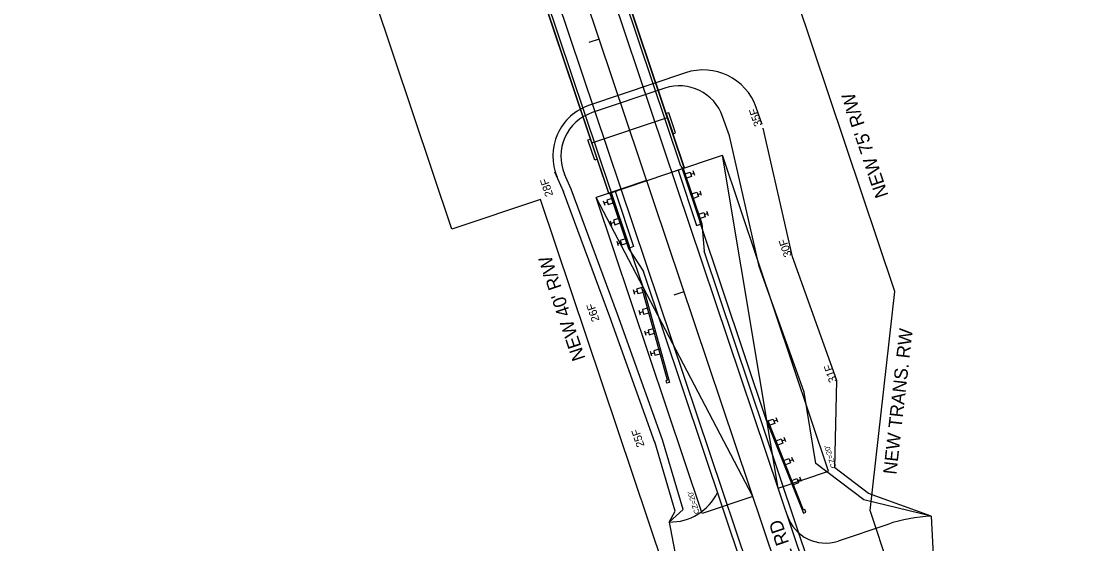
# Model space of a CAD drawing. Extents: x 1528853 to 1624411, y 1119753 to 1162242.
# Drawn here: x 1529554.1 to 1529951.4, y 1159723.3 to 1159919.3 of the extents above; entities that cross this region are included whole.
import ezdxf

# ---------------------------------------------------------------- set-up
doc = ezdxf.new("R2010")
doc.units = 0
for name, color, linetype in [('BR_CONCRETE', 7, 'Continuous'), ('RD_EX_Road Text', 7, 'Continuous'), ('RD_HC_Cl', 7, 'Continuous'), ('RD_HC_Data_Tic', 7, 'Continuous'), ('RD_PD_BOC', 7, 'Continuous'), ('RD_PD_CstnLmt', 7, 'Continuous'), ('RD_PD_CstnLmt_TX', 7, 'Continuous'), ('RD_PD_DR_ErosCtrl', 7, 'Continuous'), ('RD_PD_Driveway', 7, 'Continuous'), ('RD_PD_Final_TrvlWay', 7, 'Continuous'), ('RD_PD_GR', 7, 'Continuous'), ('RD_PD_PaveShd', 7, 'Continuous'), ('RD_PD_RW', 7, 'Continuous'), ('RD_Sketch8', 7, 'Continuous')]:
    doc.layers.add(name, color=color, linetype=linetype)

# ---------------------------------------------------------------- blocks, each defined once
blk = doc.blocks.new('Guardrail_MTBBC2_Transition')
at = {"layer": 'RD_PD_GR'}
for p, q in [((0, 0.5), (0, 0)), ((21.25, 0.5), (0, 0.5)), ((0, 0), (21.25, 0)), ((3.875, 3.75), (2.125, 3.75)), ((2.125, 0.5), (2.125, 2.5)), ((2.125, 2.5), (3.875, 2.5)), ((3.875, 0.5), (2.125, 0.5)), ((3, 2.5), (3, 3.75)), ((3.875, 2.5), (3.875, 0.5)), ((11.875, 3.75), (10.125, 3.75)), ((10.125, 0.5), (10.125, 2.5)), ((10.125, 2.5), (11.875, 2.5)), ((11.875, 0.5), (10.125, 0.5)), ((11, 2.5), (11, 3.75)), ((11.875, 2.5), (11.875, 0.5)), ((15, 0.5), (15, 0)), ((19.875, 3.75), (18.125, 3.75)), ((18.125, 0.5), (18.125, 2.5)), ((18.125, 2.5), (19.875, 2.5)), ((19.875, 0.5), (18.125, 0.5)), ((19, 2.5), (19, 3.75)), ((19.875, 2.5), (19.875, 0.5)), ((21.25, 0), (21.25, 0.5))]:
    blk.add_line(p, q, dxfattribs=at)

msp = doc.modelspace()

# ---------------------------------------------------------------- linework, layer by layer
at = {"layer": 'BR_CONCRETE'}
for p, q in [((1529801.49, 1159864.88), (1529767.1, 1159967.26)), ((1529802.75, 1159864.25), (1529767.73, 1159968.53)), ((1529802.83, 1159864.28), (1529767.81, 1159968.55)), ((1529774.39, 1159854.72), (1529739.37, 1159959)), ((1529774.47, 1159854.75), (1529739.45, 1159959.03)), ((1529775.1, 1159856.02), (1529740.71, 1159958.4)), ((1529768.03, 1159873.68), (1529796.46, 1159883.24)), ((1529774.39, 1159854.72), (1529802.83, 1159864.28)), ((1529801.49, 1159864.88), (1529802.04, 1159864.01)), ((1529775.1, 1159856.02), (1529775.18, 1159854.99))]:
    msp.add_line(p, q, dxfattribs=at)
for points in [[(1529796.93, 1159884.98), (1529795.99, 1159884.66), (1529798.53, 1159877.07), (1529799.48, 1159877.39)], [(1529766.6, 1159874.79), (1529767.55, 1159875.11), (1529770.1, 1159867.52), (1529769.15, 1159867.2)]]:
    msp.add_lwpolyline(points, close=True, dxfattribs=at)
at = {"layer": 'RD_HC_Cl'}
msp.add_line((1529913.5, 1159487.74), (1529500.12, 1160718.34), dxfattribs=at)
at = {"layer": 'RD_HC_Data_Tic'}
for p, q in [((1529770.78, 1159912.59), (1529766.99, 1159911.31)), ((1529802.62, 1159817.79), (1529798.83, 1159816.52))]:
    msp.add_line(p, q, dxfattribs=at)
at = {"layer": 'RD_PD_BOC'}
for p, q in [((1529800.38, 1159863.49), (1529807.36, 1159842.71)), ((1529802.28, 1159864.12), (1529809.26, 1159843.35)), ((1529774.87, 1159854.88), (1529781.85, 1159834.11)), ((1529776.76, 1159855.52), (1529783.74, 1159834.75)), ((1529807.36, 1159842.71), (1529809.26, 1159843.35)), ((1529783.74, 1159834.75), (1529781.85, 1159834.11))]:
    msp.add_line(p, q, dxfattribs=at)
at = {"layer": 'RD_PD_CstnLmt'}
for p, q in [((1529795.41, 1159894.16), (1529768.18, 1159885.01)), ((1529819.67, 1159876.26), (1529817.1, 1159883.57)), ((1529830.79, 1159827.25), (1529819.67, 1159876.26)), ((1529760.26, 1159856.31), (1529757.85, 1159861.96)), ((1529777.64, 1159809.4), (1529760.26, 1159856.31)), ((1529847.71, 1159780.19), (1529830.79, 1159827.25)), ((1529794.52, 1159762.32), (1529777.64, 1159809.4)), ((1529852.09, 1159753.38), (1529847.71, 1159780.19)), ((1529802.31, 1159736.15), (1529794.52, 1159762.32)), ((1529870.01, 1159739.8), (1529852.09, 1159753.38)), ((1529895.32, 1159733.63), (1529870.01, 1159739.8)), ((1529797.04, 1159731.42), (1529802.31, 1159736.15))]:
    msp.add_line(p, q, dxfattribs=at)
for centre, start, end in [((1529800.89, 1159877.87), 19.3726, 108.568), ((1529773.65, 1159868.72), 108.568, 203.162)]:
    msp.add_arc(centre, 17.19, start, end, dxfattribs=at)
at = {"layer": 'RD_PD_DR_ErosCtrl'}
for p, q in [((1529803.18, 1159899.93), (1529767.22, 1159887.85)), ((1529831.93, 1159880.57), (1529829.68, 1159886.99)), ((1529843.29, 1159830.9), (1529832.35, 1159879.14)), ((1529757.51, 1159855.13), (1529754.25, 1159862.73)), ((1529774.82, 1159808.37), (1529757.45, 1159855.26)), ((1529859.94, 1159784.59), (1529843.29, 1159830.9)), ((1529791.7, 1159761.31), (1529774.82, 1159808.37)), ((1529859.23, 1159751.73), (1529859.94, 1159784.59)), ((1529799.37, 1159735.51), (1529791.64, 1159761.47)), ((1529871.82, 1159742.19), (1529859.23, 1159751.73)), ((1529895.32, 1159733.63), (1529871.82, 1159742.19)), ((1529797.04, 1159731.42), (1529799.37, 1159735.51))]:
    msp.add_line(p, q, dxfattribs=at)
for centre, radius, start, end in [((1529809.87, 1159880.03), 21, 19.3726, 108.568), ((1529773.65, 1159868.72), 20.19, 108.568, 203.162)]:
    msp.add_arc(centre, radius, start, end, dxfattribs=at)
at = {"layer": 'RD_PD_Driveway'}
for p, q in [((1529797.04, 1159731.42), (1529800.23, 1159714.99)), ((1529895.32, 1159733.63), (1529896.42, 1159712.77)), ((1529879.01, 1159730.57), (1529860.4, 1159724.32))]:
    msp.add_line(p, q, dxfattribs=at)
for centre, radius, start, end in [((1529797.32, 1159751.42), 20, 269.2153, 333.671), ((1529855.62, 1159738.54), 15, 198.568, 288.568), ((1529898.11, 1159673.7), 60, 92.6717, 108.568)]:
    msp.add_arc(centre, radius, start, end, dxfattribs=at)
at = {"layer": 'RD_PD_Final_TrvlWay'}
for p, q in [((1529922.97, 1159490.92), (1529689.19, 1160186.88)), ((1529904.02, 1159484.55), (1529670.23, 1160180.51))]:
    msp.add_line(p, q, dxfattribs=at)
at = {"layer": 'RD_PD_GR'}
for p, q in [((1529833.73, 1159769.16), (1529808.65, 1159843.82)), ((1529787.28, 1159819.5), (1529782.11, 1159834.9)), ((1529784.14, 1159816.81), (1529783.67, 1159818.49)), ((1529786.8, 1159819.36), (1529784.87, 1159818.83)), ((1529784.87, 1159818.83), (1529785.34, 1159817.14)), ((1529786.8, 1159819.36), (1529787.28, 1159819.5)), ((1529787.27, 1159817.68), (1529786.8, 1159819.36)), ((1529796.41, 1159784.67), (1529786.8, 1159819.36)), ((1529787.28, 1159819.5), (1529797.16, 1159783.84)), ((1529785.11, 1159817.98), (1529783.9, 1159817.65)), ((1529785.34, 1159817.14), (1529787.27, 1159817.68)), ((1529786.27, 1159809.1), (1529785.8, 1159810.78)), ((1529788.94, 1159811.65), (1529787.01, 1159811.12)), ((1529787.01, 1159811.12), (1529787.48, 1159809.43)), ((1529789.4, 1159809.97), (1529788.94, 1159811.65)), ((1529787.24, 1159810.27), (1529786.04, 1159809.94)), ((1529787.48, 1159809.43), (1529789.4, 1159809.97)), ((1529788.41, 1159801.39), (1529787.94, 1159803.07)), ((1529789.38, 1159802.56), (1529788.17, 1159802.23)), ((1529791.07, 1159803.94), (1529789.14, 1159803.41)), ((1529789.14, 1159803.41), (1529789.61, 1159801.72)), ((1529791.54, 1159802.26), (1529791.07, 1159803.94)), ((1529789.61, 1159801.72), (1529791.54, 1159802.26)), ((1529790.54, 1159793.68), (1529790.07, 1159795.36)), ((1529791.51, 1159794.85), (1529790.31, 1159794.52)), ((1529793.21, 1159796.23), (1529791.28, 1159795.7)), ((1529791.28, 1159795.7), (1529791.74, 1159794.01)), ((1529793.67, 1159794.55), (1529793.21, 1159796.23)), ((1529791.74, 1159794.01), (1529793.67, 1159794.55)), ((1529795.47, 1159788.04), (1529795.95, 1159788.17)), ((1529795.92, 1159784.53), (1529796.4, 1159784.67)), ((1529796.19, 1159783.57), (1529795.92, 1159784.53)), ((1529797.16, 1159783.84), (1529796.19, 1159783.57)), ((1529834.19, 1159769.35), (1529833.73, 1159769.16)), ((1529833.73, 1159769.16), (1529847.39, 1159734.78)), ((1529834.19, 1159769.35), (1529836.05, 1159770.09)), ((1529834.84, 1159767.72), (1529834.19, 1159769.35)), ((1529847.48, 1159735.89), (1529834.19, 1159769.35)), ((1529836.7, 1159768.46), (1529834.84, 1159767.72)), ((1529836.05, 1159770.09), (1529836.7, 1159768.46)), ((1529836.37, 1159769.27), (1529837.54, 1159769.74)), ((1529837.86, 1159768.92), (1529837.21, 1159770.55)), ((1529840.81, 1159761.49), (1529840.17, 1159763.11)), ((1529837.15, 1159761.91), (1529839, 1159762.65)), ((1529837.79, 1159760.29), (1529837.15, 1159761.91)), ((1529839.65, 1159761.03), (1529837.79, 1159760.29)), ((1529839, 1159762.65), (1529839.65, 1159761.03)), ((1529839.33, 1159761.84), (1529840.49, 1159762.3)), ((1529840.1, 1159754.48), (1529841.96, 1159755.22)), ((1529841.96, 1159755.22), (1529842.6, 1159753.59)), ((1529842.28, 1159754.4), (1529843.44, 1159754.87)), ((1529843.77, 1159754.05), (1529843.12, 1159755.68)), ((1529840.74, 1159752.85), (1529840.1, 1159754.48)), ((1529842.6, 1159753.59), (1529840.74, 1159752.85)), ((1529843.05, 1159747.04), (1529844.91, 1159747.78)), ((1529843.7, 1159745.42), (1529843.05, 1159747.04)), ((1529844.91, 1159747.78), (1529845.56, 1159746.16)), ((1529845.23, 1159746.97), (1529846.4, 1159747.43)), ((1529846.72, 1159746.62), (1529846.07, 1159748.24)), ((1529845.56, 1159746.16), (1529843.7, 1159745.42)), ((1529846.19, 1159739.14), (1529845.72, 1159738.96)), ((1529847.39, 1159734.78), (1529848.32, 1159735.15)), ((1529847.95, 1159736.08), (1529847.48, 1159735.89)), ((1529848.32, 1159735.15), (1529847.95, 1159736.08))]:
    msp.add_line(p, q, dxfattribs=at)
at = {"layer": 'RD_PD_PaveShd'}
for p, q in [((1529809.33, 1159843.37), (1529810.14, 1159833.1)), ((1529781.85, 1159834.11), (1529787.4, 1159825.43)), ((1529924.87, 1159491.56), (1529810.14, 1159833.1)), ((1529902.12, 1159483.92), (1529787.4, 1159825.43))]:
    msp.add_line(p, q, dxfattribs=at)
at = {"layer": 'RD_PD_RW'}
for p, q in [((1529881.68, 1159817.98), (1529571.21, 1160742.22)), ((1529715.61, 1159841.31), (1529429.02, 1160694.46)), ((1529748.79, 1159852.45), (1529715.61, 1159841.31)), ((1529796.55, 1159710.26), (1529748.79, 1159852.45)), ((1529872.39, 1159735.73), (1529881.68, 1159817.98)), ((1529951.41, 1159500.47), (1529872.39, 1159735.73))]:
    msp.add_line(p, q, dxfattribs=at)
at = {"layer": 'RD_Sketch8'}
for p, q in [((1529798.09, 1159862.69), (1529817.05, 1159869.05)), ((1529837.9, 1159744.19), (1529817.05, 1159869.05)), ((1529856.86, 1159750.56), (1529817.05, 1159869.05)), ((1529788.61, 1159859.5), (1529769.66, 1159853.13)), ((1529828.42, 1159741.01), (1529769.66, 1159853.13)), ((1529809.46, 1159734.64), (1529769.66, 1159853.13)), ((1529837.9, 1159744.19), (1529856.86, 1159750.56)), ((1529828.42, 1159741.01), (1529809.46, 1159734.64))]:
    msp.add_line(p, q, dxfattribs=at)

# ---------------------------------------------------------------- block references
at = {"layer": 'RD_PD_BOC', "rotation": -71.4319942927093}
msp.add_blockref('Guardrail_MTBBC2_Transition', (1529801.89, 1159863.96), dxfattribs=at)
at = {"layer": 'RD_PD_BOC', "yscale": -0.9999999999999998, "rotation": -71.43199429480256}
msp.add_blockref('Guardrail_MTBBC2_Transition', (1529775.34, 1159855.04), dxfattribs=at)

# ---------------------------------------------------------------- texts
at = {"layer": 'RD_EX_Road Text'}
msp.add_text('S-26 PACE BRIDGE RD', height=5, rotation=108.5527, dxfattribs=at).set_placement((1529862.31, 1159663.38))
at = {"layer": 'RD_PD_CstnLmt_TX'}
for s, p in [('35F', (1529831.99, 1159880.4)), ('28F', (1529753.63, 1159854.08)), ('30F', (1529843.11, 1159831.39)), ('26F', (1529771.01, 1159807.17)), ('31F', (1529860.03, 1159784.33)), ('25F', (1529787.88, 1159760.09))]:
    msp.add_text(s, height=3, rotation=108.568, dxfattribs=at).set_placement(p)
at = {"layer": 'RD_PD_RW'}
for s, rotation, p in [("NEW 75' R/W", 108.5527, (1529879.35, 1159854.03)), ("NEW 40' R/W", 108.5527, (1529765.72, 1159792.86)), ('NEW TRANS. RW', 83.5511, (1529882.24, 1159749.09))]:
    msp.add_text(s, height=5, rotation=rotation, dxfattribs=at).set_placement(p)
at = {"layer": 'RD_Sketch8'}
for p in [(1529859.8, 1159752.02), (1529808.57, 1159734.81)]:
    msp.add_text("CZ=20'", height=2, rotation=108.3453, dxfattribs=at).set_placement(p)

doc.saveas('drawing.dxf')
